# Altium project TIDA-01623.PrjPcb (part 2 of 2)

## Sheet TIDA-01623-ACF_Stage.SchDoc: TIDA-01623
size 431 x 279 mm; Date: Not shown in title block; ApprovedBy: Not shown in title block; CheckedBy: Not shown in title block; Author: Not shown in title block; CompanyName: Not shown in title block; DrawnBy: Cheng Liu; Engineer: Cheng Liu; Organization: Not shown in title block; Address1: Not shown in title block; Address2: Not shown in title block; Address3: Not shown in title block; Address4: Not shown in title block; DocumentNumber: 1; Revision: Use project parameter SCH_Rev; SheetNumber: 3; SheetTotal: 4; PageSetup: Record=PageOptions¦CenterHorizontal=True¦CenterVertical=True¦PrintScale=1.00¦XCorrection=1.00¦YCorrection=1.00¦PrintKind=0¦BorderSize=5000000¦LeftOffset=0¦BottomOffset=0¦Orientation=2¦PaperLength=1000¦PaperWidth=1000¦Scale=100¦PaperSource=15¦PrintQuality=600¦MediaType=1¦DitherType=10¦PaperKind=Letter¦PrintScaleMode=1
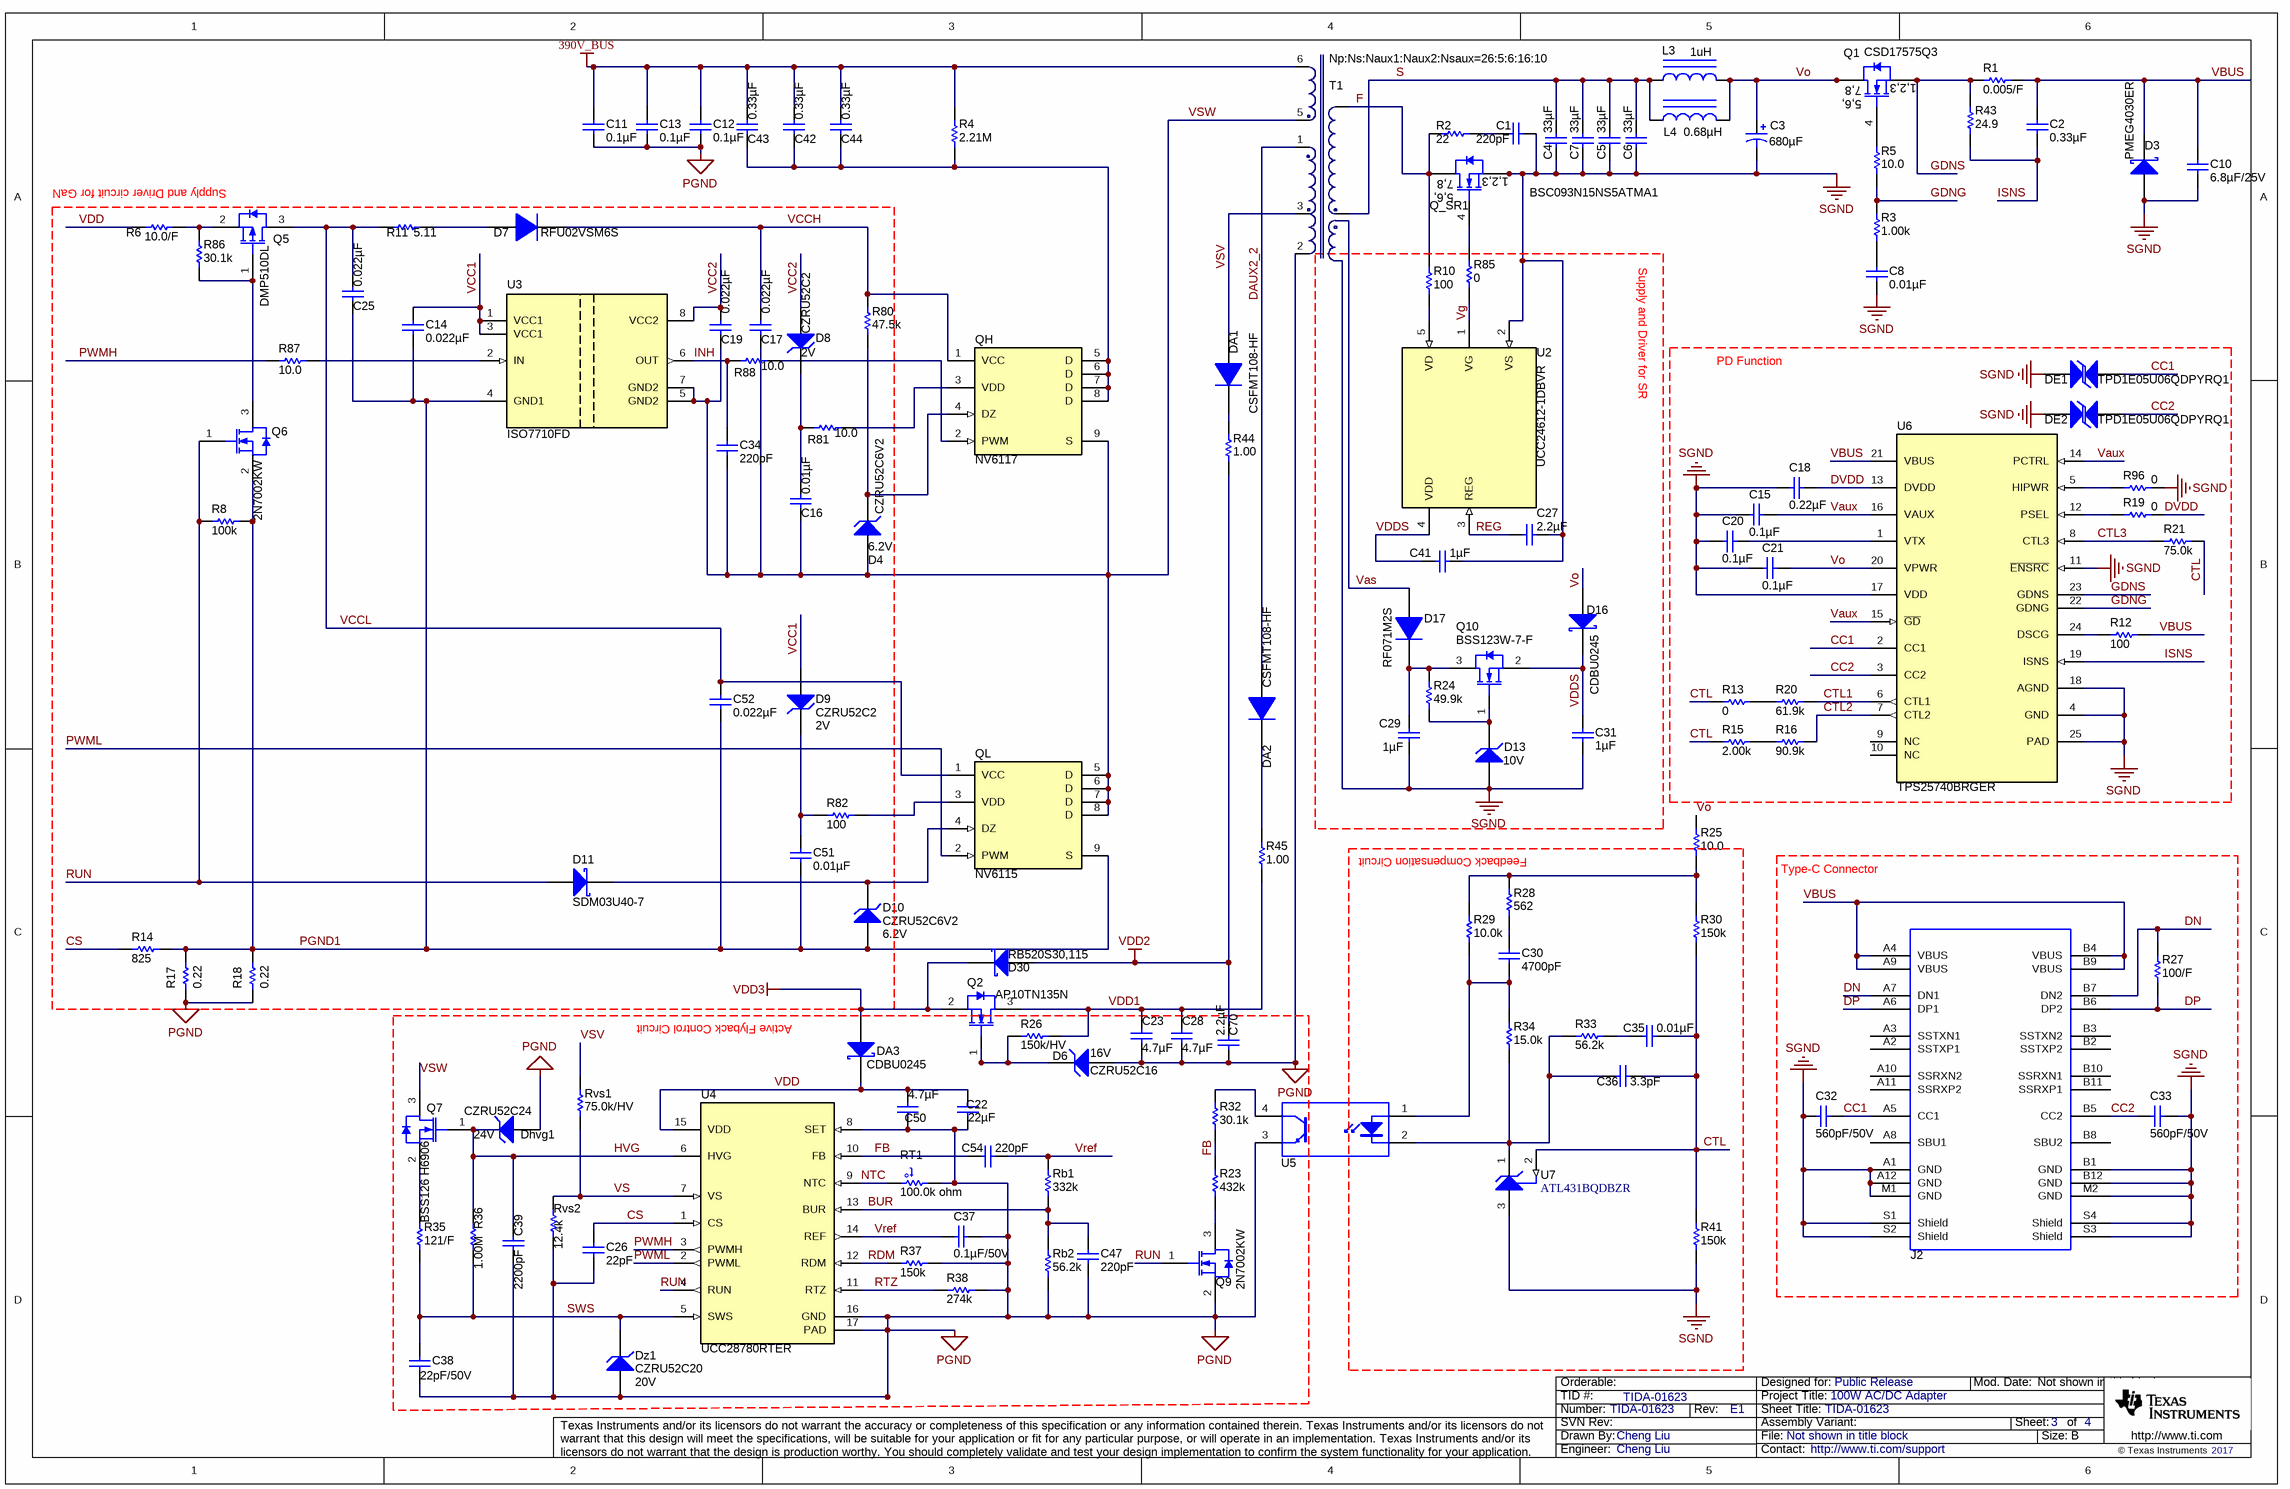
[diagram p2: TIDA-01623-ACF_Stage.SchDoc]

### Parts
C1  ValueDisplayed: 220pF  [0603S]  (hidden comment: GRM188R72E221KW07D)
C2  ValueDisplayed: 0.33µF  [0402]  (hidden comment: C1005X5R1A334K050BB)
C3  ValueDisplayed: 680µF  [PCBComponent_1]  (hidden comment: APSG200ELL681MJB5S)
C4  ValueDisplayed: 33µF  [1206_180]  (hidden comment: C3216X5R1E336M160AC)
C5  ValueDisplayed: 33µF  [1206_180]  (hidden comment: C3216X5R1E336M160AC)
C6  ValueDisplayed: 33µF  [1206_180]  (hidden comment: C3216X5R1E336M160AC)
C7  ValueDisplayed: 33µF  [1206_180]  (hidden comment: C3216X5R1E336M160AC)
C8  ValueDisplayed: 0.01µF  [0402]  (hidden comment: C0402C103J5RACTU)
C10  ValueDisplayed: 6.8µF/25V  [0805_HV1]  (hidden comment: C2012X5R1E685K125AC)
C11  ValueDisplayed: 0.1µF  [1206_180]  (hidden comment: C3216X7T2W104K160AA)
C12  ValueDisplayed: 0.1µF  [1206_180]  (hidden comment: C3216X7T2W104K160AA)
C13  ValueDisplayed: 0.1µF  [1206_180]  (hidden comment: C3216X7T2W104K160AA)
C14  ValueDisplayed: 0.022µF  [0402]  (hidden comment: GRM155R71H223KA12D)
C15  ValueDisplayed: 0.1µF  [0402]  (hidden comment: C1005X7R1H104K050BB)
C16  ValueDisplayed: 0.01µF  [0402]  (hidden comment: GCM155R71H103KA55D)
C17  ValueDisplayed: 0.022µF  [0402]  (hidden comment: GRM155R71H223KA12D)
C18  ValueDisplayed: 0.22µF  [0402]  (hidden comment: C1005X5R1E224M050BC)
C19  ValueDisplayed: 0.022µF  [0402]  (hidden comment: GRM155R71H223KA12D)
C20  ValueDisplayed: 0.1µF  [0402]  (hidden comment: C1005X7R1H104K050BB)
C21  ValueDisplayed: 0.1µF  [0603S]  (hidden comment: C0603C104K5RACTU)
C22  ValueDisplayed: 22µF  [0805_HV]  (hidden comment: C2012JB1V226M125AC)
C23  ValueDisplayed: 4.7µF  [1206_180]  (hidden comment: GRM31CZ72A475KE11)
C25  ValueDisplayed: 0.022µF  [0402]  (hidden comment: GRM155R71H223KA12D)
C26  ValueDisplayed: 22pF  [0402]  (hidden comment: GRM1555C1H220JA01D)
C27  ValueDisplayed: 2.2µF  [0603]  (hidden comment: GRM188R61H225KE11D)
C28  ValueDisplayed: 4.7µF  [1206_180]  (hidden comment: GRM31CZ72A475KE11)
C29  ValueDisplayed: 1µF  [0603]  (hidden comment: UMK107AB7105KA-T)
C30  ValueDisplayed: 4700pF  [0402]  (hidden comment: GRM155R71H472KA01D)
C31  ValueDisplayed: 1µF  [0603]  (hidden comment: UMK107AB7105KA-T)
C32  ValueDisplayed: 560pF/50V  [0603S]  (hidden comment: GRM188R71H561KA01D)
C33  ValueDisplayed: 560pF/50V  [0603]  (hidden comment: GRM188R71H561KA01D)
C34  ValueDisplayed: 220pF  [0402]  (hidden comment: GRM1555C1H221JA01D)
C35  ValueDisplayed: 0.01µF  [0402]  (hidden comment: C0402C103J5RACTU)
C36  ValueDisplayed: 3.3pF  [0402]  (hidden comment: GRM1555C1H3R3CA01D)
C37  ValueDisplayed: 0.1µF/50V  [0603S]  (hidden comment: GRM188R71H104KA93D)
C38  ValueDisplayed: 22pF/50V  [0603S]  (hidden comment: GRM1885C1H220JA01D)
C39  ValueDisplayed: 2200pF  [0603S]  (hidden comment: GRM1885C1H222JA01D)
C41  ValueDisplayed: 1µF  [0603]  (hidden comment: UMK107AB7105KA-T)
C42  ValueDisplayed: 0.33µF  [1210_220]  (hidden comment: C3225X7T2E334K200AA)
C43  ValueDisplayed: 0.33µF  [1210_220]  (hidden comment: C3225X7T2E334K200AA)
C44  ValueDisplayed: 0.33µF  [1210_220]  (hidden comment: C3225X7T2E334K200AA)
C47  ValueDisplayed: 220pF  [0402]  (hidden comment: GRM1555C1H221JA01D)
C50  ValueDisplayed: 4.7µF  [0805_HV]  (hidden comment: C2012X6S1H475K125AC)
C51  ValueDisplayed: 0.01µF  [0402]  (hidden comment: GCM155R71H103KA55D)
C52  ValueDisplayed: 0.022µF  [0402]  (hidden comment: GRM155R71H223KA12D)
C54  ValueDisplayed: 220pF  [0402]  (hidden comment: GRM1555C1H221JA01D)
C70  ValueDisplayed: 2.2µF  [0603]  (hidden comment: GRM188R61H225KE11D)
D3  PMEG4030ER  [SOD-123W]
D4  CZRU52C6V2  value 6.2V  [SOD-523F]
D6  CZRU52C16  value 16V  [SOD-523F]
D7  RFU02VSM6S  [RFU02VSM6S]
D8  CZRU52C2  value 2V  [SOD-523F]
D9  CZRU52C2  value 2V  [SOD-523F]
D10  CZRU52C6V2  value 6.2V  [SOD-523F]
D11  SDM03U40-7  [SOD-523]
D13  Vz_V: 10V  [SOD-523F]
D16  (no value)  [SOD-523F]
D17  RF071M2S  [SOD-123]
D30  RB520S30,115  [SOD-523]
DA1  CSFMT108-HF  [SOD-123H]
DA2  CSFMT108-HF  [SOD-123H]
DA3  CDBU0245  [SOD-523F]
DE1  TPD1E05U06QDPYRQ1  [DPY0002A]
DE2  TPD1E05U06QDPYRQ1  [DPY0002A]
Dhvg1  CZRU52C24  value 24V  [SOD-523F]
Dz1  CZRU52C20  value 20V  [SOD-523F]
J2  632 723 300 011  [Wurth_632_723_300_011]  (value not drawn)
L3  ValueDisplayed: 1uH  [WE-HCI_5040]  (hidden comment: 744316100)
L4  ValueDisplayed: 0.68µH  [1206L]  (hidden comment: 74479136)
Q1  CSD17575Q3  [DNH0008A]
Q2  AP10TN135N  [SOT-23]
Q5  DMP510DL  [SOT-23]
Q6  2N7002KW  [SOT-323]
Q7  BSS126 H6906  [SOT-23]
Q9  2N7002KW  [SOT-323]
Q10  BSS123W-7-F  [SOT-323]
Q_SR1  BSC093N15NS5ATMA1  [PG-TDSON-8]
QH  PartNumber: NV6117  [PQFN8_5x6]  (hidden comment: NV6115)
QL  NV6115  [PQFN8_5x6]
R1  ValueDisplayed: 0.005/F  [1206]  (hidden comment: WSL12065L000FEA)
R2  ValueDisplayed: 22  [0805_HV1]  (hidden comment: ERJ-6GEYJ220V)
R3  ValueDisplayed: 1.00k  [0402]  (hidden comment: CRCW04021K00FKED)
R4  ValueDisplayed: 2.21M  [1206]  (hidden comment: CRCW12062M21FKEA)
R5  ValueDisplayed: 10.0  [0402]  (hidden comment: CRCW040210R0FKED)
R6  ValueDisplayed: 10.0/F  [0603]  (hidden comment: CRCW060310R0FKEA)
R8  ValueDisplayed: 100k  [0402]  (hidden comment: CRCW0402100KFKED)
R10  ValueDisplayed: 100  [0603]  (hidden comment: RC0603FR-07100RL)
R11  ValueDisplayed: 5.11  [0603]  (hidden comment: CRCW06035R11FKEA)
R12  ValueDisplayed: 100  [0402]  (hidden comment: CRCW0402100RFKED)
R13  ValueDisplayed: 0  [0402]  (hidden comment: RC0402JR-070RL)
R14  ValueDisplayed: 825  [0402]  (hidden comment: CRCW0402825RFKED)
R15  ValueDisplayed: 2.00k  [0402]  (hidden comment: CRCW04022K00FKED)
R16  ValueDisplayed: 90.9k  [0402]  (hidden comment: CRCW040290K9FKED)
R17  ValueDisplayed: 0.22  [1206]  (hidden comment: ERJ-8RQFR22V)
R18  ValueDisplayed: 0.22  [1206]  (hidden comment: ERJ-8RQFR22V)
R19  ValueDisplayed: 0  [0402]  (hidden comment: CRCW04020000Z0ED)
R20  ValueDisplayed: 61.9k  [0402]  (hidden comment: CRCW040261K9FKED)
R21  ValueDisplayed: 75.0k  [0402]  (hidden comment: CRCW040275K0FKED)
R23  ValueDisplayed: 432k  [0402]  (hidden comment: CRCW0402432KFKED)
R24  ValueDisplayed: 49.9k  [0402]  (hidden comment: CRCW040249K9FKED)
R25  ValueDisplayed: 10.0  [0402]  (hidden comment: CRCW040210R0FKED)
R26  ValueDisplayed: 150k/HV  [0603]  (hidden comment: HV)
R27  ValueDisplayed: 100/F  [0603]  (hidden comment: RC0603FR-07100RL)
R28  ValueDisplayed: 562  [0402]  (hidden comment: CRCW0402562RFKED)
R29  ValueDisplayed: 10.0k  [0402]  (hidden comment: CRCW040210K0FKED)
R30  ValueDisplayed: 150k  [0402]  (hidden comment: CRCW0402150KFKED)
R32  ValueDisplayed: 30.1k  [0402]  (hidden comment: CRCW040230K1FKED)
R33  ValueDisplayed: 56.2k  [0402]  (hidden comment: CRCW040256K2FKED)
R34  ValueDisplayed: 15.0k  [0402]  (hidden comment: CRCW040215K0FKED)
R35  ValueDisplayed: 121/F  [0603S]  (hidden comment: CRCW0603121RFKEA)
R36  ValueDisplayed: 1.00M  [0402]  (hidden comment: RC0402FR-071ML)
R37  ValueDisplayed: 150k  [0402]  (hidden comment: CRCW0402150KFKED)
R38  ValueDisplayed: 274k  [0402]  (hidden comment: CRCW0402274KFKED)
R41  ValueDisplayed: 150k  [0402]  (hidden comment: CRCW0402150KFKED)
R43  ValueDisplayed: 24.9  [0603S]  (hidden comment: CRCW060324R9FKEA)
R44  ValueDisplayed: 1.00  [0805_HV]  (hidden comment: RC0805FR-071RL)
R45  ValueDisplayed: 1.00  [0805_HV]  (hidden comment: RC0805FR-071RL)
R80  ValueDisplayed: 47.5k  [0402]  (hidden comment: CRCW040247K5FKED)
R81  ValueDisplayed: 10.0  [0402]  (hidden comment: CRCW040210R0FKED)
R82  ValueDisplayed: 100  [0402]  (hidden comment: CRCW0402100RFKED)
R85  ValueDisplayed: 0  [0402]  (hidden comment: CRCW04020000Z0ED)
R86  ValueDisplayed: 30.1k  [0402]  (hidden comment: CRCW040230K1FKED)
R87  ValueDisplayed: 10.0  [0402]  (hidden comment: CRCW040210R0FKED)
R88  ValueDisplayed: 10.0  [0402]  (hidden comment: CRCW040210R0FKED)
R96  ValueDisplayed: 0  [0402]  (hidden comment: CRCW04020000Z0ED)
Rb1  ValueDisplayed: 332k  [0402]  (hidden comment: CRCW0402332KFKED)
Rb2  ValueDisplayed: 56.2k  [0402]  (hidden comment: CRCW040256K2FKED)
RT1  value 100.0k ohm  [0603]  (hidden comment: NCP18WB104F10RB)
Rvs1  ValueDisplayed: 75.0k/HV  [0603]  (hidden comment: ERJPA3F7502V)
Rvs2  ValueDisplayed: 12.4k  [0402]  (hidden comment: CRCW040212K4FKED)
T1  value Np:Ns:Naux1:Naux2:Nsaux=26:5:6:16:10  [RM4_5754]  (hidden comment: 750344183)
U2  UCC24612-1DBVR  [DBV0005A_N]
U3  ISO7710FD  [D0008A_N]
U4  UCC28780RTER  [UCC28780]
U5  FODM8801AV  [MFP04A]  (value not drawn)
U6  TPS25740BRGER  [RGE0024H]
U7  ATL431BQDBZR  [DBZ0003A_N]

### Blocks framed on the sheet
Supply and Driver circuit for GaN: C14 C16 C17 C19 C25 C34 C51 C52 D4 D7-D11 Q5 Q6 R6 R8 R11 R14 R17 R18 R80-R82 R86-R88 U3
Supply and Driver for SR: C27 C29 C31 C41 D13 D16 D17 Q10 R10 R24 R85 U2
PD Function: C15 C18 C20 C21 DE1 DE2 R12 R13 R15 R16 R19-R21 R96 U6
Feedback Compensation Circuit: C30 C35 C36 R28-R30 R33 R34 R41 U7
Type-C Connector: C32 C33 J2 R27
Active Flyback Control Circuit: C22 C23 C26 C28 C37-C39 C47 C50 C54 C70 D6 DA3 Dhvg1 Dz1 Q2 Q7 Q9 R23 R26 R32 R35-R38 Rb1 Rb2 RT1 Rvs1 Rvs2 U4

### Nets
390V_BUS: C11.2 C12.2 C13.2 C42.2 C43.2 C44.2 R4.2 T1.6
PGND: C11.1 C12.1 C13.1 C22.2 C23.2 C26.1 C28.2 C37.2 C38.2 C39.1 C47.2 C50.2 C70.2 D6.2(A) Dhvg1.2(A) Dz1.2(A) Q9.2(S) R17.1 R18.1 R37.2 R38.1 Rb2.1 RT1.1 Rvs2.1 T1.2 U4.8(SET) U4.16(GND) U4.17(PAD) U5.3(E)
SGND: C1.1 C3.2(-) C4.2 C5.2 C6.2 C7.2 C8.2 C10.2 C15.2 C18.2 C20.2 C21.2 C27.1 C29.1 C31.2 C32.2 C33.1 C41.1 D3.2(A) D13.2(A) DE1.1 DE2.1 J2.A1(GND) J2.A12(GND) J2.B1(GND) J2.B12(GND) J2.M1(GND) J2.M2(GND) J2.S1(Shield) J2.S2(Shield) J2.S3(Shield) J2.S4(Shield) Q_SR1.1(S) Q_SR1.2(S) Q_SR1.3(S) R41.1 R96.2 U2.2(VS) U6.4(GND) U6.11(~{ENSRC}) U6.17(VDD) U6.18(AGND) U6.25(PAD) U7.3(ANODE)
VDD2: C70.1 D30.2(A) R44.1
VDD3: D30.1(K) DA3.2(A) Q2.2(S)
BUR: C47.1 Rb1.1 Rb2.2 U4.13(BUR)
CC1: C32.1 DE1.2 J2.A5(CC1) U6.2(CC1)
CC2: C33.2 DE2.2 J2.B5(CC2) U6.3(CC2)
CS: C26.2 R14.1 U4.1(CS)
CTL: C35.2 C36.1 R13.1 R15.1 R21.2 R30.1 R41.2 U7.2(REF)
CTL1: R20.2 U6.6(CTL1)
CTL2: R16.2 U6.7(CTL2)
CTL3: R21.1 U6.8(CTL3)
DAUX2_2: DA2.2(A) T1.1
DN: J2.A7(DN1) J2.B7(DN2) R27.2
DP: J2.A6(DP1) J2.B6(DP2) R27.1
DVDD: C18.1 R19.2 U6.13(DVDD)
F: Q_SR1.5(D) Q_SR1.6(D) Q_SR1.7(D) Q_SR1.8(D) Q_SR1.9(D) R2.1 R10.2
FB: C54.2 R23.2 R32.1 U4.10(FB)
GDNG: R3.2 R5.1 U6.22(GDNG)
GDNS: Q1.1(S) Q1.2(S) Q1.3(S) R1.1 R43.2 U6.23(GDNS)
HVG: C39.2 Dhvg1.1(K) Q7.1(G) R36.2 U4.6(HVG)
INH: C34.2 R88.1 U3.6(OUT)
ISNS: C2.2 R43.1 U6.19(ISNS)
NTC: RT1.2 U4.9(NTC)
PGND1: C14.2 C25.2 C51.2 C52.2 D10.2(A) Q6.2(S) QL.9(S) R8.1 R14.2 R17.2 R18.2 U3.4(GND1)
PWMH: R87.1 U4.3(PWMH)
PWML: QL.2(PWM) U4.2(PWML)
RDM: R37.1 U4.12(RDM)
REG: C27.2 U2.3(REG)
RTZ: R38.2 U4.11(RTZ)
RUN: D11.2(A) Q6.1(G) Q9.1(G) R8.2 U4.4(RUN)
S: C4.1 C5.1 C6.1 C7.1 L3.1 L4.1
SWS: C38.1 Dz1.1(K) R35.1 R36.1 U4.5(SWS)
Vas: D17.2(A)
Vaux: C15.1 U6.14(PCTRL) U6.15(~{GD}) U6.16(VAUX)
VBUS: C2.1 C10.1 D3.1(K) J2.A4(VBUS) J2.A9(VBUS) J2.B4(VBUS) J2.B9(VBUS) R1.2 R12.2 U6.21(VBUS)
VCC1: C14.1 D9.2(A) U3.1(VCC1) U3.3(VCC1)
VCC2: C19.1 D8.2(A) U3.8(VCC2)
VCCH: C17.1 D7.1(K) QH.1(VCC) R80.2
VCCL: C25.1 C52.1 Q5.3(D) QL.1(VCC) R11.2
VDD: C22.1 C50.1 DA3.1(K) R6.1 U4.15(VDD)
VDD1: C23.1 C28.1 Q2.3(D) R26.2 R45.1
VDDS: C31.1 C41.2 D16.1(K) Q10.2(S) U2.4(VDD)
Vg: R85.2 U2.1(VG)
Vo: C3.1(+) C21.1 D16.2(A) L3.2 L4.2 Q1.5(D) Q1.6(D) Q1.7(D) Q1.8(D) Q1.9(D) R25.2 U6.20(VPWR)
Vref: C37.1 C54.1 Rb1.2 U4.14(REF)
VS: Rvs1.1 Rvs2.2 U4.7(VS)
VSV: DA1.2(A) Rvs1.2 T1.3
VSW: C16.2 C17.2 C19.2 C34.1 D4.2(A) Q7.3(D) QH.9(S) QL.5(D) QL.6(D) QL.7(D) QL.8(D) T1.5 U3.5(GND2) U3.7(GND2)
NetC1_2: C1.2 R2.2
NetC8_1: C8.1 R3.1
NetC16_1: C16.1 D8.1(K) R81.2
NetC20_1: C20.1 U6.1(VTX)
NetC29_2: C29.2 D17.1(K) Q10.3(D) R24.1
NetC30_1: C30.1 R28.1
NetC30_2: C30.2 R29.1 R34.2 U5.1(A)
NetC35_1: C35.1 R33.2
NetC36_2: C36.2 R33.1 R34.1 U5.2(K) U7.1(CATHODE)
NetC42_1: C42.1 C43.1 C44.1 QH.5(D) QH.6(D) QH.7(D) QH.8(D) R4.1
NetC51_1: C51.1 D9.1(K) R82.2
NetD4_1: D4.1(K) QH.4(DZ) R80.1
NetD6_1: D6.1(K) Q2.1(G) R26.1
NetD7_2: D7.2(A) R11.1
NetD10_1: D10.1(K) D11.1(K) QL.4(DZ)
NetD13_1: D13.1(K) Q10.1(G) R24.2
NetDA1_1: DA1.1(K) R44.2
NetDA2_1: DA2.1(K) R45.2
NetQ1_4: Q1.4(G) R5.2
NetQ5_1: Q5.1(G) Q6.3(D) R86.1
NetQ5_2: Q5.2(S) R6.2 R86.2
NetQ7_2: Q7.2(S) R35.2
NetQ9_3: Q9.3(D) R23.1
NetQ_SR1_4: Q_SR1.4(G) R85.1
NetQH_2: QH.2(PWM) R88.2
NetQH_3: QH.3(VDD) R81.1
NetQL_3: QL.3(VDD) R82.1
NetR10_1: R10.1 U2.5(VD)
NetR12_1: R12.1 U6.24(DSCG)
NetR13_2: R13.2 R20.1
NetR15_2: R15.2 R16.1
NetR19_1: R19.1 U6.12(PSEL)
NetR25_1: R25.1 R28.2 R29.2 R30.2
NetR32_2: R32.2 U5.4(C)
NetR87_2: R87.2 U3.2(IN)
NetR96_1: R96.1 U6.5(HIPWR)

Not connected (* = marked no-connect by the designer): J2 A2(SSTXP1) A3(SSTXN1) A8(SBU1) A10(SSRXN2) A11(SSRXP2) B2(SSTXP2) B3(SSTXN2) B8(SBU2) B10(SSRXN1) B11(SSRXP1); U6 9(NC) 10(NC)

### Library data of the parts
C1 = GRM188R72E221KW07D: CAP, CERM, 220 pF, 250 V, +/- 10%, X7R, 0603; Manufacturer: MuRata; Polarized: N; CompType: Capacitor; Value: 220pF; U/M: EA; Cap_F: 0.00000000022; Tolerance_%: 10; Value1: Unknown; VDC_V: 250; Value2: 250V; TaMin_C: -55; TaMax_C: 125; Cap_Case: 0603; SizeArea_mm2: 1.28; SizeAreaWB_mm2: 4.68; SizeX_mm: 1.6; SizeY_mm: 0.8; SizeZ_mm: 1; AEC Category: Q200
C2 = C1005X5R1A334K050BB: CAP, CERM, 0.33 µF, 10 V, +/- 10%, X5R, 0402; Manufacturer: TDK; Polarized: N; CompType: Capacitor; Value: 0.33uF; U/M: EA; Cap_F: 0.00000033; Tolerance_%: 10; Value1: Unknown; Value2: 10V; TaMin_C: -55; TaMax_C: 85; SizeArea_mm2: 0.5; SizeAreaWB_mm2: 3; SizeX_mm: 1; SizeZ_mm: 0.6; AEC Category: Q200
C3 = APSG200ELL681MJB5S: CAP, Aluminum Polymer, 680 µF, 20 V, +/- 20%, 0.012 ohm, TH; Manufacturer: Chemi-Con; Polarized: Y; CompType: Capacitor; Value: 680uF; U/M: EA; Cap_F: 0.00068; Tolerance_%: 20; ESR_ohm: 0.012; Value2: 20V; IRMS_A: 5.4; TaMin_C: -55; TaMax_C: 105; Cap_Case: 10x11.5; SizeArea_mm2: 100; SizeAreaWB_mm2: 144; SizeX_mm: 10; SizeZ_mm: 13; AEC Category: Q200; AEC Qualified: N
C4-C7 = C3216X5R1E336M160AC: CAP, CERM, 33 µF, 25 V, +/- 20%, X5R, 1206; Manufacturer: TDK; Polarized: N; CompType: Capacitor; Value: 33uF; U/M: EA; Cap_F: 0.000033; Tolerance_%: 20; ESR_ohm: 0.002648; Value1: 0.002648 ohm; VDC_V: 25; Value2: 25V; IRMS_A: 4.45864; TaMin_C: -55; TaMax_C: 85; SizeArea_mm2: 5.12; SizeAreaWB_mm2: 10.92; SizeX_mm: 3.2; SizeY_mm: 1.6; SizeZ_mm: 1.8; AEC Category: Q200
C8 C35 = C0402C103J5RACTU: CAP, CERM, 0.01 µF, 50 V, +/- 5%, X7R, 0402; Manufacturer: Kemet; Polarized: N; CompType: Capacitor; Value: 0.01uF; U/M: EA; Cap_F: 0.00000001; Tolerance_%: 5; Value1: Unknown; VDC_V: 50; Value2: 50V; TaMin_C: -55; TaMax_C: 125; SizeArea_mm2: 0.5; SizeAreaWB_mm2: 3; SizeX_mm: 1; SizeZ_mm: 0.6; AEC Category: Q200
C10 = C2012X5R1E685K125AC: CAP, CERM, 6.8 µF, 25 V, +/- 10%, X5R, 0805; Manufacturer: TDK; Polarized: N; CompType: Capacitor; Value: 6.8uF; U/M: EA; Cap_F: 0.0000068; Tolerance_%: 10; Value1: Unknown; VDC_V: 25; Value2: 25V; TaMin_C: -55; TaMax_C: 85; Cap_Case: 0805; SizeArea_mm2: 2.5; SizeAreaWB_mm2: 6.75; SizeX_mm: 2; SizeY_mm: 1.25; SizeZ_mm: 1.45; AEC Category: Q200
C11-C13 = GRM31CR72E104KW03L: CAP, CERM, 0.1 µF, 450 V, +/- 10%, X7T, 1206; Manufacturer: MuRata; Polarized: N; CompType: Capacitor; Value: 0.1uF; U/M: EA; Cap_F: 0.0000001; Tolerance_%: 10; Value1: Unknown; VDC_V: 450V; TempCo: X7R; TaMin_C: -55; TaMax_C: 125; Cap_Case: 1206; SizeArea_mm2: 5.12; SizeAreaWB_mm2: 10.92; SizeX_mm: 3.2; SizeY_mm: 1.6; SizeZ_mm: 1.8; AEC Category: Q200
C14 C17 C19 C25 C52 = GRM155R71H223KA12D: CAP, CERM, 0.022 µF, 50 V, +/- 10%, X7R, 0402; Manufacturer: MuRata; Polarized: N; CompType: Capacitor; Value: 0.022uF; U/M: EA; Cap_F: 0.000000022; Tolerance_%: 10; Value1: Unknown; VDC_V: 50; Value2: 50V; TaMin_C: -55; TaMax_C: 125; SizeArea_mm2: 0.5; SizeAreaWB_mm2: 3; SizeX_mm: 1; SizeZ_mm: 0.6; AEC Category: Q200
C15 C20 = C1005X7R1H104K050BB: CAP, CERM, 0.1 µF, 50 V, +/- 10%, X7R, 0402; Manufacturer: TDK; Polarized: N; CompType: Capacitor; Value: 0.1uF; U/M: EA; Cap_F: 0.0000001; Tolerance_%: 10; ESR_ohm: 0.039064; Value1: 0.039064 ohm; VDC_V: 50; Value2: 50V; IRMS_A: 0.814669; TaMin_C: -55; TaMax_C: 125; SizeArea_mm2: 0.5; SizeAreaWB_mm2: 3; SizeX_mm: 1; SizeZ_mm: 0.6; AEC Category: Q200
C16 C51 = GCM155R71H103KA55D: CAP, CERM, 0.01 µF, 50 V, +/- 10%, C0G/NP0, 0402; Manufacturer: MuRata; Polarized: N; CompType: Capacitor; Value: 0.01uF; U/M: EA; Cap_F: 0.00000001; Tolerance_%: 10; Value1: Unknown; VDC_V: 50; Value2: 50V; TaMin_C: -55; TaMax_C: 125; SizeArea_mm2: 0.5; SizeAreaWB_mm2: 3; SizeX_mm: 1; SizeZ_mm: 0.6; AEC Category: Q200
C18 = C1005X5R1E224M050BC: CAP, CERM, 0.22 µF, 25 V, +/- 20%, X5R, 0402; Manufacturer: TDK; Polarized: N; CompType: Capacitor; Value: 0.22uF; U/M: EA; Cap_F: 0.00000022; Tolerance_%: 20; Value1: Unknown; VDC_V: 25; Value2: 25V; TaMin_C: -55; TaMax_C: 85; SizeArea_mm2: 0.5; SizeAreaWB_mm2: 3; SizeX_mm: 1; SizeZ_mm: 0.6; AEC Category: Q200
C21 = C0603C104K5RACTU: CAP, CERM, 0.1 µF, 50 V, +/- 10%, X7R, 0603; Manufacturer: Kemet; Polarized: N; CompType: Capacitor; Value: 0.1uF; U/M: EA; Cap_F: 0.0000001; Tolerance_%: 10; Value1: Unknown; VDC_V: 50; Value2: 50V; TaMin_C: -55; TaMax_C: 125; Cap_Case: 0603; SizeArea_mm2: 1.28; SizeAreaWB_mm2: 4.68; SizeX_mm: 1.6; SizeY_mm: 0.8; SizeZ_mm: 1; AEC Category: Q200
C22 = C2012JB1V226M125AC: CAP, CERM, 22 µF, 35 V, +/- 20%, JB, 0805; Manufacturer: TDK; Polarized: N; CompType: Capacitor; Value: 22uF; U/M: EA; Cap_F: 0.000022; Tolerance_%: 20; Value1: Unknown; VDC_V: 35; Value2: 35V; TaMin_C: -25; TaMax_C: 85; Cap_Case: 0805; SizeArea_mm2: 2.5; SizeAreaWB_mm2: 6.75; SizeX_mm: 2; SizeY_mm: 1.25; SizeZ_mm: 1.45; AEC Category: Q200
C23 C28 = GRM31CR71H475KA12L: CAP, CERM, 4.7 µF, 100 V, +/- 10%, X7R, 1206; Manufacturer: MuRata; Polarized: N; CompType: Capacitor; Value: 4.7uF; U/M: EA; Cap_F: 0.0000047; Tolerance_%: 10; Value1: Unknown; VDC_V: 100V; TaMin_C: -55; TaMax_C: 125; Cap_Case: 2220; SizeArea_mm2: 5.12; SizeAreaWB_mm2: 10.92; SizeX_mm: 3.2; SizeY_mm: 1.6; SizeZ_mm: 1.8; AEC Category: Q200
C26 = GRM1555C1H220JA01D: CAP, CERM, 22 pF, 50 V, +/- 5%, C0G/NP0, 0402; Manufacturer: MuRata; Polarized: N; CompType: Capacitor; Value: 22pF; U/M: EA; Cap_F: 0.000000000022; Tolerance_%: 5; Value1: Unknown; VDC_V: 50; Value2: 50V; TaMin_C: -55; TaMax_C: 125; SizeArea_mm2: 0.5; SizeAreaWB_mm2: 3; SizeX_mm: 1; SizeZ_mm: 0.6; AEC Category: Q200
C27 C70 = GRM188R61H225KE11D: CAP, CERM, 2.2 µF, 50 V, +/- 10%, X5R, 0603; Manufacturer: MuRata; Polarized: N; CompType: Capacitor; Value: 2.2uF; U/M: EA; Cap_F: 0.0000022; Tolerance_%: 10; Value1: Unknown; VDC_V: 50; Value2: 50V; TaMin_C: -55; TaMax_C: 85; SizeArea_mm2: 1.28; SizeAreaWB_mm2: 4.68; SizeX_mm: 1.6; SizeY_mm: 0.8; SizeZ_mm: 1; AEC Category: Q200
C29 C31 C41 = UMK107AB7105KA-T: CAP, CERM, 1 µF, 50 V, +/- 10%, X7R, 0603; Manufacturer: Taiyo Yuden; Polarized: N; CompType: Capacitor; Value: 1uF; U/M: EA; Cap_F: 0.000001; Tolerance_%: 10; Value1: Unknown; VDC_V: 50; Value2: 50V; TaMin_C: -55; TaMax_C: 125; SizeArea_mm2: 1.28; SizeAreaWB_mm2: 4.68; SizeX_mm: 1.6; SizeY_mm: 0.8; SizeZ_mm: 1; AEC Category: Q200
C30 = GRM155R71H472KA01D: CAP, CERM, 4700 pF, 50 V, +/- 10%, X7R, 0402; Manufacturer: MuRata; Polarized: N; CompType: Capacitor; Value: 4700pF; U/M: EA; Cap_F: 0.0000000047; Tolerance_%: 10; Value1: Unknown; VDC_V: 50; Value2: 50V; TaMin_C: -55; TaMax_C: 125; SizeArea_mm2: 0.5; SizeAreaWB_mm2: 3; SizeX_mm: 1; SizeZ_mm: 0.6; AEC Category: Q200
C32 = GRM188R71H561KA01D: CAP, CERM, 560 pF, 50 V, +/- 10%, X7R, 0603; Manufacturer: MuRata; Polarized: N; CompType: Capacitor; Value: 560pF; U/M: EA; Cap_F: 0.00000000056; Tolerance_%: 10; Value1: Unknown; VDC_V: 50; Value2: 50V; TaMin_C: -55; TaMax_C: 125; Cap_Case: 0603; SizeArea_mm2: 1.28; SizeAreaWB_mm2: 4.68; SizeX_mm: 1.6; SizeY_mm: 0.8; SizeZ_mm: 1; AEC Category: Q200
C33 = GRM188R71H561KA01D: CAP, CERM, 560 pF, 50 V, +/- 10%, X7R, 0603; Manufacturer: MuRata; Polarized: N; CompType: Capacitor; Value: 560pF; U/M: EA; Cap_F: 0.00000000056; Tolerance_%: 10; Value1: Unknown; VDC_V: 50; Value2: 50V; TaMin_C: -55; TaMax_C: 125; SizeArea_mm2: 1.28; SizeAreaWB_mm2: 4.68; SizeX_mm: 1.6; SizeY_mm: 0.8; SizeZ_mm: 1; AEC Category: Q200
C34 C47 C54 = GRM1555C1H221JA01D: CAP, CERM, 220 pF, 50 V, +/- 5%, C0G/NP0, 0402; Manufacturer: MuRata; Polarized: N; CompType: Capacitor; Value: 220pF; U/M: EA; Cap_F: 0.00000000022; Tolerance_%: 5; Value1: Unknown; VDC_V: 50; Value2: 50V; TaMin_C: -55; TaMax_C: 125; SizeArea_mm2: 0.5; SizeAreaWB_mm2: 3; SizeX_mm: 1; SizeZ_mm: 0.6; AEC Category: Q200
C36 = GRM1555C1H3R3CA01D: CAP, CERM, 3.3 pF, 50 V, +/- 5%, C0G/NP0, 0402; Manufacturer: MuRata; Polarized: N; CompType: Capacitor; Value: 3.3pF; U/M: EA; Cap_F: 0.0000000000033; Tolerance_%: 5; Value1: Unknown; VDC_V: 50; Value2: 50V; TaMin_C: -55; TaMax_C: 125; SizeArea_mm2: 0.5; SizeAreaWB_mm2: 3; SizeX_mm: 1; SizeZ_mm: 0.6; AEC Category: Q200
C37 = GRM188R71H104KA93D: CAP, CERM, 0.1 µF, 50 V, +/- 10%, X7R, 0603; Manufacturer: MuRata; Polarized: N; CompType: Capacitor; Value: 0.1uF; U/M: EA; Cap_F: 0.0000001; Tolerance_%: 10; Value1: Unknown; VDC_V: 50; Value2: 50V; TaMin_C: -55; TaMax_C: 125; Cap_Case: 0603; SizeArea_mm2: 1.28; SizeAreaWB_mm2: 4.68; SizeX_mm: 1.6; SizeY_mm: 0.8; SizeZ_mm: 1; AEC Category: Q200
C38 = GRM1885C1H220JA01D: CAP, CERM, 22 pF, 50 V, +/- 5%, C0G/NP0, 0603; Manufacturer: MuRata; Polarized: N; CompType: Capacitor; Value: 22pF; U/M: EA; Cap_F: 0.000000000022; Tolerance_%: 5; Value1: Unknown; VDC_V: 50; Value2: 50V; TaMin_C: -55; TaMax_C: 125; Cap_Case: 0603; SizeArea_mm2: 1.28; SizeAreaWB_mm2: 4.68; SizeX_mm: 1.6; SizeY_mm: 0.8; SizeZ_mm: 1; AEC Category: Q200
C39 = GRM1885C1H222JA01D: CAP, CERM, 2200 pF, 50 V, +/- 5%, C0G/NP0, 0603; Manufacturer: MuRata; Polarized: N; CompType: Capacitor; Value: 2200pF; U/M: EA; Cap_F: 0.0000000022; Tolerance_%: 5; Value1: Unknown; VDC_V: 50; Value2: 50V; TaMin_C: -55; TaMax_C: 125; Cap_Case: 0603; SizeArea_mm2: 1.28; SizeAreaWB_mm2: 4.68; SizeX_mm: 1.6; SizeY_mm: 0.8; SizeZ_mm: 1; AEC Category: Q200
C42-C44 = C3225X7R2A334K200AA: CAP, CERM, 0.33 µF, 250 V, +/- 10%, X7T, 1210; Manufacturer: TDK; Polarized: N; CompType: Capacitor; Value: 0.33uF; U/M: EA; Cap_F: 0.00000033; Tolerance_%: 10; ESR_ohm: 0.010566; Value1: 0.010566 ohm; VDC_V: 250; Value2: 250V; IRMS_A: 2.2725; TaMin_C: -55; TaMax_C: 125; SizeArea_mm2: 8; SizeAreaWB_mm2: 14.7; SizeX_mm: 3.2; SizeY_mm: 2.5; SizeZ_mm: 2.2; AEC Category: Q200
C50 = C2012X6S1H475K125AC: CAP, CERM, 4.7 µF, 50 V, +/- 10%, X6S, 0805; Manufacturer: TDK; Polarized: N; CompType: Capacitor; Value: 4.7uF; U/M: EA; Cap_F: 0.0000047; Tolerance_%: 10; ESR_ohm: 0.002346; Value1: 0.002346 ohm; VDC_V: 50; Value2: 50V; IRMS_A: 4.26021; TaMin_C: -55; TaMax_C: 105; Cap_Case: 0805; SizeArea_mm2: 2.5; SizeAreaWB_mm2: 6.75; SizeX_mm: 2; SizeY_mm: 1.25; SizeZ_mm: 1.45; AEC Category: Q200
D3 = PMEG10010ELRX: Diode, Schottky, 40 V, 3 A, AEC-Q101, SOD-123W; Manufacturer: NXP Semiconductor; U/M: EA; Vf_V: 0.77; Value: 40V; Value1: 3A; Value2: 0.77V; Io_A: 1; Vr_V: 100; TJmax_C: 175; SizeAreaWB_mm2: 12.15; SizeArea_mm2: 5.95; SizeX_mm: 3.5; SizeY_mm: 1.7; AEC Category: Q101; AEC Qualified: Y
D4 D10 = CZRU52C5V6: Diode, Zener, 6.2 V, 150 mW, SOD-523F; Manufacturer: Comchip Technology; SymbolCreator: a0412235; U/M: EA; Power_W: 0.15; Vz_V: 5.6; Value1: 0.15W; SizeAreaWB_mm2: 5.13; SizeArea_mm2: 1.53; SizeX_mm: 1.7; SizeY_mm: 0.9; SizeZ_mm: 0.85; AEC Category: Q101
D6 = CZRU52C5V6: Diode, Zener, 16 V, 150 mW, SOD-523F; Manufacturer: Comchip Technology; SymbolCreator: a0412235; U/M: EA; Power_W: 0.15; Vz_V: 16; Value1: 0.15W; SizeAreaWB_mm2: 5.13; SizeArea_mm2: 1.53; SizeX_mm: 1.7; SizeY_mm: 0.9; SizeZ_mm: 0.85; AEC Category: Q101
D7 = RFU02VSM6S: Diode, Superfast Rectifier, 600 V, 0.2A; Manufacturer: Comchip Technology; U/M: EA; Vf_V: 1.7; Value: 600V; Value1: 1A; Value2: 1.7V; Io_A: 1; Vr_V: 600; TJmax_C: 150; SizeAreaWB_mm2: 11.7; SizeArea_mm2: 5.6; SizeX_mm: 3.5; SizeY_mm: 1.6; AEC Category: Q101; AEC Qualified: N
D8 D9 = CZRU52C5V6: Diode, Zener, 2 V, 150 mW, SOD-523F; Manufacturer: Comchip Technology; SymbolCreator: a0412235; U/M: EA; Power_W: 0.15; Vz_V: 5.6; Value1: 0.15W; SizeAreaWB_mm2: 5.13; SizeArea_mm2: 1.53; SizeX_mm: 1.7; SizeY_mm: 0.9; SizeZ_mm: 0.85; AEC Category: Q101
D11 = SDM03U40-7: Diode, Schottky, 40 V, 0.03 A, SOD-523; Manufacturer: Diodes Inc.; U/M: EA; Vf_V: 1; Value: 40V; Value1: 0.03A; Value2: 1V; Io_A: 0.03; Vr_V: 40; TJmax_C: 125; SizeAreaWB_mm2: 5.13; SizeArea_mm2: 1.53; SizeX_mm: 1.7; SizeY_mm: 0.9; SizeZ_mm: 0.65; AEC Category: Q101
D13 = CZRU52C5V6: Diode, Zener, 10V, 150 mW, SOD-523F; PartNumber: CZRU52C10V; Manufacturer: Comchip Technology; SymbolCreator: a0412235; U/M: EA; Power_W: 0.15; Value1: 0.15W; SizeAreaWB_mm2: 5.13; SizeArea_mm2: 1.53; SizeX_mm: 1.7; SizeY_mm: 0.9; SizeZ_mm: 0.85; AEC Category: Q101
D16 DA3 = CDBU0245: Diode, Schottky, 50 V, 0.2 A, SOD-523F; Manufacturer: Comchip Technology; U/M: EA; Vf_V: 0.55; Value: 50V; Value1: 0.2A; Value2: 0.55V; Io_A: 0.2; Vr_V: 50; TJmax_C: 125; SizeAreaWB_mm2: 5.13; SizeArea_mm2: 1.53; SizeX_mm: 1.7; SizeY_mm: 0.9; SizeZ_mm: 0.85; AEC Category: Q101; AEC Qualified: N
D17 = RF071M2S: Diode, Ultrafast, 200 V, 1 A, SOD-123; Manufacturer: Rohm; U/M: EA; Vf_V: 0.85; Value: 200V; Value1: 1A; Value2: 0.85V; Io_A: 1; Vr_V: 200; TJmax_C: 150; SizeAreaWB_mm2: 13.095; SizeArea_mm2: 6.545; SizeX_mm: 3.85; SizeY_mm: 1.7; SizeZ_mm: 1.35; AEC Category: Q101
D30 = RB520S30,115: Diode, Schottky, 30 V, 0.2 A, SOD-523; Manufacturer: NXP Semiconductor; U/M: EA; Vf_V: 0.6; Value: 30V; Value1: 0.2A; Value2: 0.6V; Io_A: 0.2; Vr_V: 30; TJmax_C: 150; SizeAreaWB_mm2: 5.13; SizeArea_mm2: 1.53; SizeX_mm: 1.7; SizeY_mm: 0.9; SizeZ_mm: 0.65; AEC Category: Q101
DA1 DA2 = CSFMT108-HF: Diode, Superfast Rectifier, 600 V, 1 A, 3.5x1.6mm; Manufacturer: Comchip Technology; U/M: EA; Vf_V: 1.7; Value: 600V; Value1: 1A; Value2: 1.7V; Io_A: 1; Vr_V: 600; TJmax_C: 150; SizeAreaWB_mm2: 11.7; SizeArea_mm2: 5.6; SizeX_mm: 3.5; SizeY_mm: 1.6; AEC Category: Q101; AEC Qualified: N
DE1 DE2 = TPD1E0B04DPYR: 1-Channel ESD Protection Diode for USB Type-C and Antenna Protection, DPY0002A (X1SON-2); Manufacturer: Texas Instruments; CompType: IC; SizeArea_mm2: 0.6; SizeAreaWB_mm2: 3.2; SizeX_mm: 1; SizeZ_mm: 0.45; U/M: EA
Dhvg1 = CZRU52C5V6: Diode, Zener, 24 V, 150 mW, SOD-523F; Manufacturer: Comchip Technology; U/M: EA; Power_W: 0.15; Vz_V: 24; Value1: 0.15W; SizeAreaWB_mm2: 5.13; SizeArea_mm2: 1.53; SizeX_mm: 1.7; SizeY_mm: 0.9; SizeZ_mm: 0.85; AEC Category: Q101; SymbolCreator: a0412235
Dz1 = CZRU52C5V6: Diode, Zener, 20 V, 150 mW, SOD-523F; Manufacturer: Comchip Technology; U/M: EA; Power_W: 0.15; Vz_V: 20; Value1: 0.15W; SizeAreaWB_mm2: 5.13; SizeArea_mm2: 1.53; SizeX_mm: 1.7; SizeY_mm: 0.9; SizeZ_mm: 0.85; AEC Category: Q101; SymbolCreator: a0412235
J2 = 632 723 300 011: Connector, Receptacle, USB Type C, R/A; Manufacturer: Wurth Elektronik; SymbolCreator: a0412235; Gender: Female; ContactFinish: Gold; Current_A: 3; Voltage_V: 5; Cert_UL: Y
L3 = 744316022: FIXED IND 1UH 11.5A 4.75 MOHM; Manufacturer: Wurth Elektronik; CompType: Inductor; Ind_H: 220.0E-9; Imax_A: 20; Irms: 20A @ 40C rise; Isat: 25A @ 30% inductance drop; DCR_ohm: 0.00125; Value1: 0.00125 ohm; Value2: 20A; SizeAreaWB_mm2: 55.48; SizeArea_mm2: 29.68; SizeX_mm: 5.6; SizeY_mm: 5.3; SizeZ_mm: 4.3; AEC Category: Q200; AEC Qualified: N
L4 = 744042330: Inductor, Multilayer, Ferrite, 0.68 μH, 0.19 A, 0.67  ohm, 1206; Manufacturer: Wurth Elektronik; Value: 0.68uH; Ind_H: 33.0E-6; Imax_A: 0.5; Irms: 0.72A @ 30C rise; Isat: 0.5A @ 35% inductance drop; DCR_ohm: 0.382; Value1: 0.382 ohm; Value2: 0.5A; Material: Metal Composite; SizeAreaWB_mm2: 33.64; SizeArea_mm2: 23.04; SizeX_mm: 4.8; SizeZ_mm: 2; AEC Category: Q200
Q1 = CSD17578Q3A: MOSFET, N-CH, 30 V, 27 A, DNH0008A (VSONP-8); Manufacturer: Texas Instruments; Alternate Manufacturer: None; U/M: EA; ChType: N; Value: 30V; VdsMax_V: 30; Value1: 0.0019 ohm; Rdson45_ohm: 0.0082; Value2: 7.9 nC; QgTyp_nC: 7.9; Vgs_V: 20; IdsMax_A: 14; SizeAreaWB_mm2: 18.49; SizeArea_mm2: 10.89; SizeX_mm: 3.3; SizeZ_mm: 0.9; AEC Category: Q101
Q2 = PMV213SN,215: MOSFET, N-CH, 100 V, 1.9 A, SOT-23; Manufacturer: Advanced Power; Alternate Manufacturer: None; Value: 100V; Value1: ? ohm; Value2: 7 nC; U/M: EA; AEC Category: Q101; AEC Qualified: N; VdsMax_V: 100; QgTyp_nC: 7; Vgs_V: 30; IdsMax_A: 1.9; SizeAreaWB_mm2: 14; SizeArea_mm2: 7.5; SizeX_mm: 2.5; SizeY_mm: 3; SizeZ_mm: 1.1
Q5 = DMP3099L-7: 'MOSFET P-CH 50V 0.18A SOT23; PartNumber: DMP510DL-7; Manufacturer: Diodes Inc.; Alternate Manufacturer: None; CompType: MOSFET; U/M: EA; ChType: P; Value: -30V; VdsMax_V: -30; Value1: ? ohm; Value2: 5.2 nC; QgTyp_nC: 5.2; Vgs_V: -20; IdsMax_A: -3.8; SizeAreaWB_mm2: 14; SizeArea_mm2: 7.5; SizeX_mm: 2.5; SizeY_mm: 3; SizeZ_mm: 1.1; AEC Category: Q101; AEC Qualified: Y
Q6 Q9 = 2N7002KW: MOSFET, N-CH, 60 V, 0.31 A, SOT-323; Manufacturer: Fairchild Semiconductor; Alternate Manufacturer: None; U/M: EA; ChType: N; Value: 60V; VdsMax_V: 60; Value1: 1.6 ohm; Rdson45_ohm: 1.6; Value2: ? nC; Vgs_V: 2.1; IdsMax_A: 0.31; SizeAreaWB_mm2: 10.24; SizeArea_mm2: 4.84; SizeX_mm: 2.2; SizeZ_mm: 1.1; AEC Category: Q101
Q7 = BSS126 H6906: MOSFET, N-CH, 600 V, 0.021 A, AEC-Q101, SOT-23; Manufacturer: Infineon Technologies; Alternate Manufacturer: None; SymbolCreator: a0412235; U/M: EA; ChType: N; Value: 600V; VdsMax_V: 600; Value1: ? ohm; Value2: 1.4 nC; QgTyp_nC: 1.4; Vgs_V: 20; IdsMax_A: 0.021; SizeAreaWB_mm2: 14; SizeArea_mm2: 7.5; SizeX_mm: 2.5; SizeY_mm: 3; SizeZ_mm: 1.1; AEC Category: Q101; AEC Qualified: Y
Q10 = BSS123W-7-F: MOSFET, N-CH, 100 V, 0.17 A, SOT-323; Manufacturer: Diodes Inc.; Alternate Manufacturer: None; Value: 100V; Value1: 10 ohm; Value2: ? nC; U/M: EA; AEC Category: Q101; ChType: N; VdsMax_V: 100; Rdson45_ohm: 10; Vgs_V: 20; IdsMax_A: 0.17; SizeAreaWB_mm2: 10.24; SizeArea_mm2: 4.84; SizeX_mm: 2.2; SizeZ_mm: 1.1
Q_SR1 = BSC093N15NS5ATMA1: MOSFET, N-CH, 150 V, 87 A, PG-TDSON-8; Manufacturer: Infineon Technologies; Alternate Manufacturer: None; U/M: EA; ChType: N; Value: 150V; VdsMax_V: 150; Value1: ? ohm; Value2: 33 nC; QgTyp_nC: 33; Vgs_V: 20; IdsMax_A: 87; SizeAreaWB_mm2: 55.131; SizeArea_mm2: 29.351; SizeX_mm: 5.99; SizeY_mm: 4.9; SizeZ_mm: 1.12; AEC Category: Q101
QH QL = CMP-0077886-1: 650V AllGaN Power IC with iDrive, PQFN-8; Manufacturer: Navitas Semiconductor
R1 = WSL12065L000FEA: RES, 0.005, 1%, 0.25 W, 1206; Manufacturer: Vishay-Dale; CompType: Resistor; Value: 0.005; Value_Code: 5L000; Tolerance_%: 1; Power_W: 0.25; Value2: 0.25W; TempCo: 110 ppm/C; SizeArea_mm2: 5.12; SizeX_mm: 3.2; SizeY_mm: 1.6; SizeZ_mm: 1.35; EIA_Code: E96; U/M: EA; AEC Category: Q200; AEC Qualified: N
R2 = ERJ-6GEYJ220V: RES, 22, 5%, 0.125 W, 0805; Manufacturer: Panasonic; CompType: Resistor; Value: 22; Value_Code: 22R0; Tolerance_%: 5; Power_W: 0.125; Value2: 0.125W; VDC_V: 150; TempCo: 200 ppm/C; SizeArea_mm2: 2.5; SizeX_mm: 2; SizeY_mm: 1.25; SizeZ_mm: 1.45; EIA_Code: E24; U/M: EA; AEC Category: Q200
R3 = CRCW04021K00FKED: RES, 1.00 k, 1%, 0.063 W, 0402; Manufacturer: Vishay-Dale; CompType: Resistor; Value: 1.00k; Res_ohm: 1000; Value_Code: 1k00; Tolerance_%: 1; Power_W: 0.063; Value2: 0.063W; VDC_V: 50; TempCo: 100 ppm/C; SizeArea_mm2: 0.5; SizeZ_mm: 0.6; EIA_Code: E96; U/M: EA; AEC Category: Q200
R4 = CRCW12062M21FKEA: RES, 2.21 M, 1%, 0.25 W, 1206; Manufacturer: Vishay-Dale; CompType: Resistor; Value: 2.21Meg; Res_ohm: 2210000; Value_Code: 2M21; Tolerance_%: 1; Power_W: 0.25; Value2: 0.25W; VDC_V: 200; TempCo: 100 ppm/C; SizeArea_mm2: 5.12; SizeX_mm: 3.2; SizeY_mm: 1.6; SizeZ_mm: 1.35; EIA_Code: E96; U/M: EA; AEC Category: Q200
R5 R25 R81 R87 R88 = CRCW040210R0FKED: RES, 10.0, 1%, 0.063 W, 0402; Manufacturer: Vishay-Dale; CompType: Resistor; Value: 10.0; Res_ohm: 10; Value_Code: 10R0; Tolerance_%: 1; Power_W: 0.063; Value2: 0.063W; VDC_V: 50; TempCo: 100 ppm/C; SizeArea_mm2: 0.5; SizeZ_mm: 0.6; EIA_Code: E96; U/M: EA; AEC Category: Q200
R6 = CRCW060310R0FKEA: RES, 10.0, 1%, 0.1 W, 0603; Manufacturer: Vishay-Dale; CompType: Resistor; Value: 10.0; Res_ohm: 10; Value_Code: 10R0; Tolerance_%: 1; Power_W: 0.1; Value2: 0.1W; VDC_V: 75; TempCo: 100 ppm/C; SizeArea_mm2: 1.28; SizeX_mm: 1.6; SizeY_mm: 0.8; EIA_Code: E96; U/M: EA; AEC Category: Q200
R8 = CRCW0402100KFKED: RES, 100 k, 1%, 0.063 W, 0402; Manufacturer: Vishay-Dale; CompType: Resistor; Value: 100k; Res_ohm: 100000; Tolerance_%: 1; Power_W: 0.063; Value2: 0.063W; VDC_V: 50; TempCo: 100 ppm/C; SizeArea_mm2: 0.5; SizeZ_mm: 0.6; EIA_Code: E96; U/M: EA; AEC Category: Q200
R10 R27 = RC0603FR-07100RL: RES, 100, 1%, 0.1 W, 0603; Manufacturer: Yageo America; CompType: Resistor; Value: 100; Value_Code: 100R; Tolerance_%: 1; Power_W: 0.1; Value2: 0.1W; VDC_V: 150; TempCo: 200 ppm/C; SizeArea_mm2: 1.28; SizeX_mm: 1.6; SizeY_mm: 0.8; EIA_Code: E96; U/M: EA; AEC Category: Q200
R11 = CRCW06035R11FKEA: RES, 5.11, 1%, 0.1 W, 0603; Manufacturer: Vishay-Dale; CompType: Resistor; Value: 5.11; Value_Code: 5R11; Tolerance_%: 1; Power_W: 0.1; Value2: 0.1W; VDC_V: 75; TempCo: 100 ppm/C; SizeArea_mm2: 1.28; SizeX_mm: 1.6; SizeY_mm: 0.8; EIA_Code: E96; U/M: EA; AEC Category: Q200
R12 R82 = CRCW0402100RFKED: RES, 100, 1%, 0.063 W, 0402; Manufacturer: Vishay-Dale; CompType: Resistor; Value: 100; Value_Code: 100R; Tolerance_%: 1; Power_W: 0.063; Value2: 0.063W; VDC_V: 50; TempCo: 100 ppm/C; SizeArea_mm2: 0.5; SizeZ_mm: 0.6; EIA_Code: E96; U/M: EA; AEC Category: Q200
R13 = RC0402JR-070RL: RES, 0, 5%, 0.063 W, 0402; Manufacturer: Yageo America; CompType: Resistor; Value: 0; Value_Code: 0000; Tolerance_%: 5; Power_W: 0.063; Value2: 0.063W; VDC_V: 50; TempCo: 200 ppm/C; SizeArea_mm2: 0.5; SizeX_mm: 1; SizeZ_mm: 0.6; EIA_Code: E24; U/M: EA; AEC Category: Q200
R14 = CRCW0402825RFKED: RES, 825, 1%, 0.063 W, 0402; Manufacturer: Vishay-Dale; CompType: Resistor; Value: 825; Value_Code: 825R; Tolerance_%: 1; Power_W: 0.063; Value2: 0.063W; VDC_V: 50; TempCo: 100 ppm/C; SizeArea_mm2: 0.5; SizeZ_mm: 0.6; EIA_Code: E96; U/M: EA; AEC Category: Q200
R15 = CRCW04022K00FKED: RES, 2.00 k, 1%, 0.063 W, 0402; Manufacturer: Vishay-Dale; CompType: Resistor; Value: 2.00k; Res_ohm: 2000; Value_Code: 2k00; Tolerance_%: 1; Power_W: 0.063; Value2: 0.063W; VDC_V: 50; TempCo: 100 ppm/C; SizeArea_mm2: 0.5; SizeZ_mm: 0.6; EIA_Code: E96; U/M: EA; AEC Category: Q200
R16 = CRCW040290K9FKED: RES, 90.9 k, 1%, 0.063 W, 0402; Manufacturer: Vishay-Dale; CompType: Resistor; Value: 90.9k; Res_ohm: 90900; Value_Code: 90k9; Tolerance_%: 1; Power_W: 0.063; Value2: 0.063W; VDC_V: 50; TempCo: 100 ppm/C; SizeArea_mm2: 0.5; SizeZ_mm: 0.6; EIA_Code: E96; U/M: EA; AEC Category: Q200
R17 R18 = ERJ-8RQFR22V: RES, 0.22, 1%, 0.25 W, 1206; Manufacturer: Panasonic; CompType: Resistor; Value: 0.22; Value_Code: R220; Tolerance_%: 1; Power_W: 0.25; Value2: 0.25W; TempCo: 250 ppm/C; SizeArea_mm2: 5.12; SizeX_mm: 3.2; SizeY_mm: 1.6; SizeZ_mm: 1.35; EIA_Code: E96; U/M: EA; AEC Category: Q200
R19 R85 R96 = CRCW04020000Z0ED: RES, 0, 5%, 0.063 W, 0402; Manufacturer: Vishay-Dale; CompType: Resistor; Value: 0; Value_Code: 0000; Tolerance_%: 5; Power_W: 0.063; Value2: 0.063W; VDC_V: 50; TempCo: 200 ppm/C; SizeArea_mm2: 0.5; SizeX_mm: 1; SizeZ_mm: 0.6; EIA_Code: E24; U/M: EA; AEC Category: Q200
R20 = CRCW040261K9FKED: RES, 61.9 k, 1%, 0.063 W, 0402; Manufacturer: Vishay-Dale; CompType: Resistor; Value: 61.9k; Res_ohm: 61900; Value_Code: 61k9; Tolerance_%: 1; Power_W: 0.063; Value2: 0.063W; VDC_V: 50; TempCo: 100 ppm/C; SizeArea_mm2: 0.5; SizeZ_mm: 0.6; EIA_Code: E96; U/M: EA; AEC Category: Q200
R21 = CRCW040275K0FKED: RES, 75.0 k, 1%, 0.063 W, 0402; Manufacturer: Vishay-Dale; CompType: Resistor; Value: 75.0k; Res_ohm: 75000; Value_Code: 75k0; Tolerance_%: 1; Power_W: 0.063; Value2: 0.063W; VDC_V: 50; TempCo: 100 ppm/C; SizeArea_mm2: 0.5; SizeZ_mm: 0.6; EIA_Code: E96; U/M: EA; AEC Category: Q200
R23 = CRCW0402432KFKED: RES, 432 k, 1%, 0.063 W, 0402; Manufacturer: Vishay-Dale; CompType: Resistor; Value: 432k; Res_ohm: 432000; Tolerance_%: 1; Power_W: 0.063; Value2: 0.063W; VDC_V: 50; TempCo: 100 ppm/C; SizeArea_mm2: 0.5; SizeZ_mm: 0.6; EIA_Code: E96; U/M: EA; AEC Category: Q200
R24 = CRCW040249K9FKED: RES, 49.9 k, 1%, 0.063 W, 0402; Manufacturer: Vishay-Dale; CompType: Resistor; Value: 49.9k; Res_ohm: 49900; Value_Code: 49k9; Tolerance_%: 1; Power_W: 0.063; Value2: 0.063W; VDC_V: 50; TempCo: 100 ppm/C; SizeArea_mm2: 0.5; SizeZ_mm: 0.6; EIA_Code: E96; U/M: EA; AEC Category: Q200
R26 = CRCW0603150KFKEA: RES, 150 k, 1%, 0.1 W, 0603; Manufacturer: Vishay-Dale; CompType: Resistor; Value: 150k; Res_ohm: 150000; Tolerance_%: 1; Power_W: 0.1; Value2: 0.1W; VDC_V: 75; TempCo: 100 ppm/C; SizeArea_mm2: 1.28; SizeX_mm: 1.6; SizeY_mm: 0.8; EIA_Code: E96; U/M: EA; AEC Category: Q200
R28 = CRCW0402562RFKED: RES, 562, 1%, 0.063 W, 0402; Manufacturer: Vishay-Dale; CompType: Resistor; Value: 562; Value_Code: 562R; Tolerance_%: 1; Power_W: 0.063; Value2: 0.063W; VDC_V: 50; TempCo: 100 ppm/C; SizeArea_mm2: 0.5; SizeZ_mm: 0.6; EIA_Code: E96; U/M: EA; AEC Category: Q200
R29 = CRCW040210K0FKED: RES, 10.0 k, 1%, 0.063 W, 0402; Manufacturer: Vishay-Dale; CompType: Resistor; Value: 10.0k; Res_ohm: 10000; Value_Code: 10k0; Tolerance_%: 1; Power_W: 0.063; Value2: 0.063W; VDC_V: 50; TempCo: 100 ppm/C; SizeArea_mm2: 0.5; SizeZ_mm: 0.6; EIA_Code: E96; U/M: EA; AEC Category: Q200
R30 R37 R41 = CRCW0402150KFKED: RES, 150 k, 1%, 0.063 W, 0402; Manufacturer: Vishay-Dale; CompType: Resistor; Value: 150k; Res_ohm: 150000; Tolerance_%: 1; Power_W: 0.063; Value2: 0.063W; VDC_V: 50; TempCo: 100 ppm/C; SizeArea_mm2: 0.5; SizeZ_mm: 0.6; EIA_Code: E96; U/M: EA; AEC Category: Q200
R32 R86 = CRCW040230K1FKED: RES, 30.1 k, 1%, 0.063 W, 0402; Manufacturer: Vishay-Dale; CompType: Resistor; Value: 30.1k; Res_ohm: 30100; Value_Code: 30k1; Tolerance_%: 1; Power_W: 0.063; Value2: 0.063W; VDC_V: 50; TempCo: 100 ppm/C; SizeArea_mm2: 0.5; SizeZ_mm: 0.6; EIA_Code: E96; U/M: EA; AEC Category: Q200
R33 Rb2 = CRCW040256K2FKED: RES, 56.2 k, 1%, 0.063 W, 0402; Manufacturer: Vishay-Dale; CompType: Resistor; Value: 56.2k; Res_ohm: 56200; Value_Code: 56k2; Tolerance_%: 1; Power_W: 0.063; Value2: 0.063W; VDC_V: 50; TempCo: 100 ppm/C; SizeArea_mm2: 0.5; SizeZ_mm: 0.6; EIA_Code: E96; U/M: EA; AEC Category: Q200
R34 = CRCW040215K0FKED: RES, 15.0 k, 1%, 0.063 W, 0402; Manufacturer: Vishay-Dale; CompType: Resistor; Value: 15.0k; Res_ohm: 15000; Value_Code: 15k0; Tolerance_%: 1; Power_W: 0.063; Value2: 0.063W; VDC_V: 50; TempCo: 100 ppm/C; SizeArea_mm2: 0.5; SizeZ_mm: 0.6; EIA_Code: E96; U/M: EA; AEC Category: Q200
R35 = CRCW0603121RFKEA: RES, 121, 1%, 0.1 W, 0603; Manufacturer: Vishay-Dale; CompType: Resistor; Value: 121; Value_Code: 121R; Tolerance_%: 1; Power_W: 0.1; Value2: 0.1W; VDC_V: 75; TempCo: 100 ppm/C; SizeArea_mm2: 1.28; SizeX_mm: 1.6; SizeY_mm: 0.8; EIA_Code: E96; U/M: EA; AEC Category: Q200
R36 = RC0402FR-071ML: RES, 1.00 M, 1%, 0.063 W, 0402; Manufacturer: Yageo America; CompType: Resistor; Value: 1.00Meg; Res_ohm: 1000000; Value_Code: 1M00; Tolerance_%: 1; Power_W: 0.063; Value2: 0.063W; TempCo: 100 ppm/C; SizeArea_mm2: 0.5; SizeZ_mm: 0.6; EIA_Code: E96; U/M: EA; AEC Category: Q200
R38 = CRCW0402274KFKED: RES, 274 k, 1%, 0.063 W, 0402; Manufacturer: Vishay-Dale; CompType: Resistor; Value: 274k; Res_ohm: 274000; Tolerance_%: 1; Power_W: 0.063; Value2: 0.063W; VDC_V: 50; TempCo: 100 ppm/C; SizeArea_mm2: 0.5; SizeZ_mm: 0.6; EIA_Code: E96; U/M: EA; AEC Category: Q200
R43 = CRCW060324R9FKEA: RES, 24.9, 1%, 0.1 W, 0603; Manufacturer: Vishay-Dale; CompType: Resistor; Value: 24.9; Value_Code: 24R9; Tolerance_%: 1; Power_W: 0.1; Value2: 0.1W; VDC_V: 75; TempCo: 100 ppm/C; SizeArea_mm2: 1.28; SizeX_mm: 1.6; SizeY_mm: 0.8; EIA_Code: E96; U/M: EA; AEC Category: Q200
R44 R45 = RC0805FR-071RL: RES, 1.00, 1%, 0.125 W, 0805; Manufacturer: Yageo America; CompType: Resistor; Value: 1.00; Res_ohm: 1; Value_Code: 1R00; Power_W: 0.125; Value2: 0.125W; VDC_V: 150; TempCo: 200 ppm/C; SizeArea_mm2: 2.5; SizeX_mm: 2; SizeY_mm: 1.25; SizeZ_mm: 1.45; EIA_Code: E96; U/M: EA; AEC Category: Q200
R80 = CRCW040247K5FKED: RES, 47.5 k, 1%, 0.063 W, 0402; Manufacturer: Vishay-Dale; CompType: Resistor; Value: 47.5k; Res_ohm: 47500; Value_Code: 47k5; Tolerance_%: 1; Power_W: 0.063; Value2: 0.063W; VDC_V: 50; TempCo: 100 ppm/C; SizeArea_mm2: 0.5; SizeZ_mm: 0.6; EIA_Code: E96; U/M: EA; AEC Category: Q200
Rb1 = CRCW0402332KFKED: RES, 332 k, 1%, 0.063 W, 0402; Manufacturer: Vishay-Dale; CompType: Resistor; Value: 332k; Res_ohm: 332000; Tolerance_%: 1; Power_W: 0.063; Value2: 0.063W; VDC_V: 50; TempCo: 100 ppm/C; SizeArea_mm2: 0.5; SizeZ_mm: 0.6; EIA_Code: E96; U/M: EA; AEC Category: Q200
RT1 = NCP18WB473F10RB: Thermistor NTC, 100.0k ohm, 1%, 0603; Manufacturer: MuRata; Tolerance_%: 1; Power_W: 0.1; TaMin_C: -40; TaMax_C: 125; U/M: EA
Rvs1 = CRCW060375K0FKEA: RES, 75.0 k, 1%, 0.1 W, 0603; Manufacturer: Panasonic; CompType: Resistor; Value: 75.0k; Res_ohm: 75000; Value_Code: 75k0; Tolerance_%: 1; Power_W: 0.1; Value2: 0.1W; VDC_V: 150; TempCo: 100 ppm/C; SizeArea_mm2: 1.28; SizeX_mm: 1.6; SizeY_mm: 0.8; EIA_Code: E96; U/M: EA; AEC Category: Q200
Rvs2 = CRCW040212K4FKED: RES, 12.4 k, 1%, 0.063 W, 0402; Manufacturer: Vishay-Dale; CompType: Resistor; Value: 12.4k; Res_ohm: 12400; Value_Code: 12k4; Tolerance_%: 1; Power_W: 0.063; Value2: 0.063W; VDC_V: 50; TempCo: 100 ppm/C; SizeArea_mm2: 0.5; SizeZ_mm: 0.6; EIA_Code: E96; U/M: EA; AEC Category: Q200
T1 = Transformer: Transformer, 110 uH, RM10; Manufacturer: Wurth Elektronik; SymbolCreator: Altium; Lp: 95uH; DCR_ohm: 0.24
U2 = UCC24612-1DBVR: UCC24612-1DBV, DBV0005A (SOT-23-5); Alternate PartNumber: UCC24612-1DBVT; Manufacturer: Texas Instruments; SymbolCreator: Altium; SizeArea_mm2: 8.12; SizeAreaWB_mm2: 14.82; SizeX_mm: 2.8; SizeY_mm: 2.9; SizeZ_mm: 1.45; CompType: IC; U/M: EA
U3 = ISO7310CDR: Robust EMC, Low Power, Single Channel Digital Isolator, D0008A (SOIC-8); Manufacturer: Texas Instruments; SymbolCreator: a0411947; SizeArea_mm2: 30.38; SizeAreaWB_mm2: 56.58; SizeX_mm: 4.9; SizeY_mm: 6.2; SizeZ_mm: 1.75; CompType: IC; U/M: EA
U4 = UCC28780RTER: Active-Clamp Flyback Controller, RTE0016C (WQFN-16); Manufacturer: Texas Instruments; SymbolCreator: Altium; SizeArea_mm2: 9; SizeAreaWB_mm2: 16; SizeX_mm: 3; SizeZ_mm: 0.8; CompType: IC; U/M: EA
U5 = HMHA2801A: Optocoupler, 3.75 kV, 80-160% CTR, SMT; Manufacturer: Fairchild Semiconductor; CTR (Min): 80%; CTR (Max): 160%; Voltage_Isolation_Vrms: 3750V; SizeAreaWB_mm2: 4; SizeArea_mm2: 1
U6 = TPS25740BRGER: USB Type-C and USB PD Source Controller, RGE0024H (VQFN-24); Alternate PartNumber: TPS25740BRGET; Manufacturer: Texas Instruments; SymbolCreator: a0411947; SizeArea_mm2: 16; SizeAreaWB_mm2: 25; SizeX_mm: 4; SizeZ_mm: 1; CompType: IC; U/M: EA
U7 = TL431ACDBZR: Adjustable Precision Shunt Regulator, 34 ppm / degC, 100 mA, 0 to 70 degC, 3-pin SOT-23 (DBZ), Green (RoHS & no Sb/Br); Manufacturer: Texas Instruments; Alternate PartNumber: Equivalent; Initial Accuracy @ 25/deg C(%): 1; Iout/Iz(Max)(mA): 100; Min Iz for Regulation(uA): 600; Rating: Catalog; SubFamily: Shunt Voltage Reference; Temp Coeff(Typ)(ppm/ degree C): 34; VO Adj(Max)(V): 36; VO Adj(Min)(V): 2.495

## Sheet TIDA-01623_Hardware.SchDoc: Hardware
size 431 x 279 mm; Date: Not shown in title block; ApprovedBy: Not shown in title block; CheckedBy: Not shown in title block; Author: Not shown in title block; CompanyName: Not shown in title block; DrawnBy: Cheng Liu; Engineer: Cheng Liu; Organization: Not shown in title block; Address1: Not shown in title block; Address2: Not shown in title block; Address3: Not shown in title block; Address4: Not shown in title block; DocumentNumber: 1; Revision: Use project parameter SCH_Rev; SheetNumber: 4; SheetTotal: 4; PageSetup: Record=PageOptions¦CenterHorizontal=True¦CenterVertical=True¦PrintScale=1.00¦XCorrection=1.00¦YCorrection=1.00¦PrintKind=0¦BorderSize=5000000¦LeftOffset=0¦BottomOffset=0¦Orientation=2¦PaperLength=1000¦PaperWidth=1000¦Scale=100¦PaperSource=15¦PrintQuality=600¦MediaType=1¦DitherType=10¦PaperKind=Letter¦PrintScaleMode=1
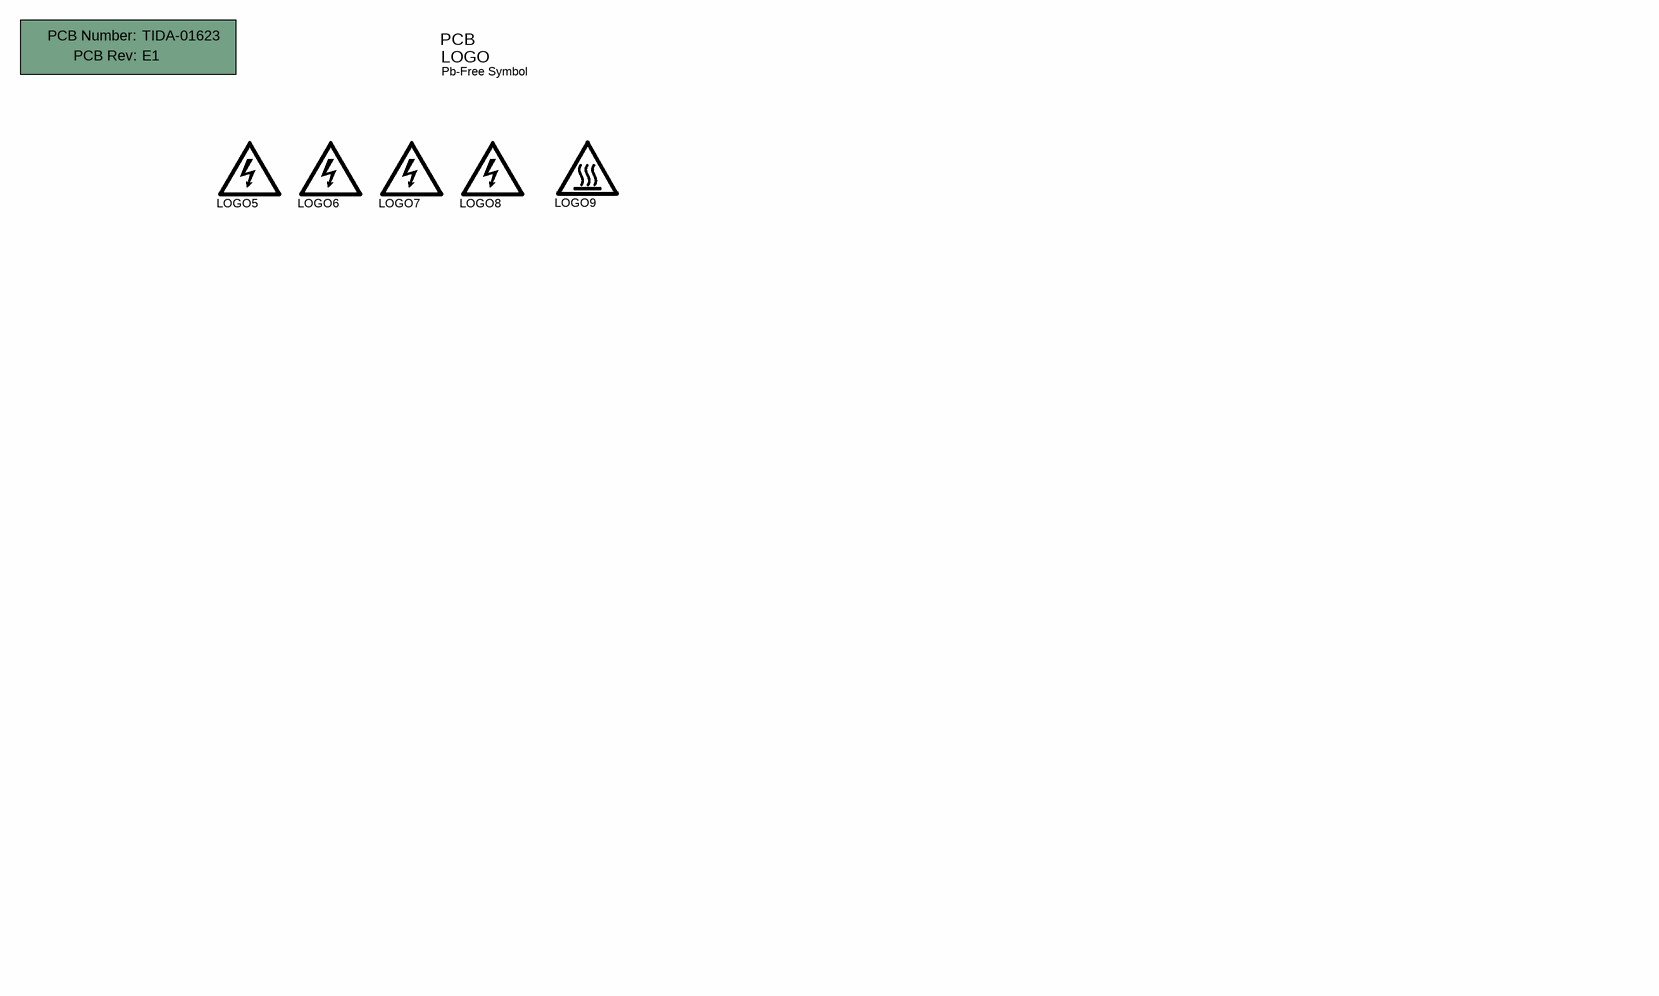
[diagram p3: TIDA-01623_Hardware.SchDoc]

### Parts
!PCB1  Printed Circuit Board  (value not drawn)  (mechanical)
Logo2  Pb-Free Symbol  [Pb-Free_Overlay_Small]  (no BOM)
LOGO5  DANGER HIGH VOLTAGE  [IEC_HighVoltage_Small]  (value not drawn)  (no BOM)
LOGO6  DANGER HIGH VOLTAGE  [IEC_HighVoltage_Small]  (value not drawn)  (no BOM)
LOGO7  DANGER HIGH VOLTAGE  [IEC_HighVoltage_Small]  (value not drawn)  (no BOM)
LOGO8  DANGER HIGH VOLTAGE  [IEC_HighVoltage_Small]  (value not drawn)  (no BOM)
LOGO9  CAUTION HOT SURFACE  [IEC_HotSurface_Small]  (value not drawn)  (no BOM)

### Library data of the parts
!PCB1 = PCB: Manufacturer: Any; PartNumber: TIDA-01623; SymbolCreator: a0412235
Logo2 = Pb-Free: SymbolCreator: a0412235
LOGO5-LOGO8 = IEC_HighVoltage: IEC 61010-1 High Voltage Warning; SymbolCreator: a0412235
LOGO9 = IEC_HotSurface: IEC 61010-1 Hot Surface Warning; SymbolCreator: a0412235

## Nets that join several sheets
390V_BUS: TIDA-01623_PFC_Stage (5 pins), TIDA-01623-ACF_Stage (8 pins)
PGND: TIDA-01623_PFC_Stage (30 pins), TIDA-01623-ACF_Stage (29 pins)
VDD2: TIDA-01623_PFC_Stage (D25.1 R31.1), TIDA-01623-ACF_Stage (C70.1 D30.2 R44.1)
VDD3: TIDA-01623_PFC_Stage (C78.2 D19.2 U11.1 U11.3), TIDA-01623-ACF_Stage (D30.1 DA3.2 Q2.2)

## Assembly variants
001: not fitted 12V,18A C1 C12 FID1 FID2 FID3 J1 R1 R9 SGND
